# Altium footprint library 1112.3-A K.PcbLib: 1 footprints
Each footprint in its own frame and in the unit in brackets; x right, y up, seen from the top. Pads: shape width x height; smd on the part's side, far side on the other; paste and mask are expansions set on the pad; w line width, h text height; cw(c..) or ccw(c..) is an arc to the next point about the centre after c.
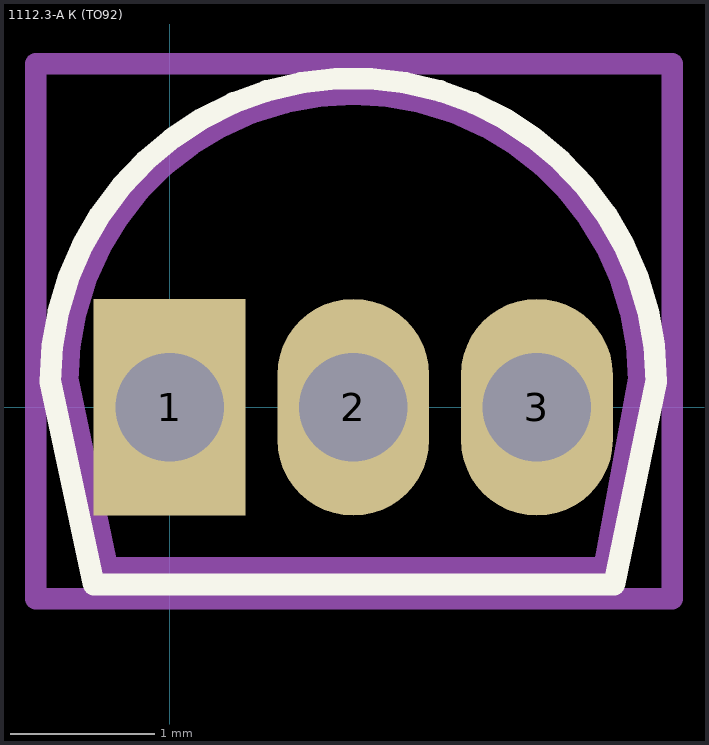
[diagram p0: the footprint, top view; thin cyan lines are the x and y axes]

## 1112.3-А К (TO92) [mm]
pads (3):
  rect 1.05x1.5 hole 0.75: 1(0,0)
  rrect100% 1.05x1.5 hole 0.75: 2(1.27,0) 3(2.54,0)
F.SilkS:
  lines w0.15: -0.825,0.18 cw(c1.27,0.18) 3.365,0.18 3.075,-1.225 -0.525,-1.225 -0.825,0.18
F.CrtYd:
  lines w0.15: -0.925,-1.325 -0.925,2.375 3.475,2.375 3.475,-1.325 -0.925,-1.325
F.Fab:
  lines w0.15: 2.969,-1.11 -0.429,-1.11 -0.705,0.19 cw(c1.27,0.19) 3.245,0.19 3.004,-1.11
3D body "1112.3-A K.step": height 7, standoff -2.5, extent -0.696,-1.11 3.236,2.156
